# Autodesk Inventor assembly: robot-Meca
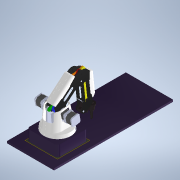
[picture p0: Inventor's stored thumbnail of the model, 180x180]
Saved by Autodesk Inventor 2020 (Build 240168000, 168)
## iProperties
Created: 2017-09
Part Number: robot-Meca
Document SubType Name: Assembly
Designer: bruno
Sending System: SolidWorks 2016
Last Author: Prof
Last Saved: 2018-10-31
Author: bruno
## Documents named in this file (11)
- C:\Users\bruno\Documents\1-Cours-2023-24\1SI\Robot-Dobot\Robot-meca\robot-Meca.iam
- C:\Users\bruno\Documents\1-Cours-2023-24\1SI\Robot-Dobot\Robot-meca\base^robot.iam
- C:\Users\bruno\Documents\1-Cours-2023-24\1SI\Robot-Dobot\Robot-meca\plateforme^robot.iam
- C:\Users\bruno\Documents\1-Cours-2023-24\1SI\Robot-Dobot\Robot-meca\bras inférieur^robot.iam
- C:\Users\bruno\Documents\1-Cours-2023-24\1SI\Robot-Dobot\Robot-meca\manivelle inférieure^robot.iam
- C:\Users\bruno\Documents\1-Cours-2023-24\1SI\Robot-Dobot\Robot-meca\biellette gauche^robot.iam
- C:\Users\bruno\Documents\1-Cours-2023-24\1SI\Robot-Dobot\Robot-meca\biellette droite^robot.iam
- C:\Users\bruno\Documents\1-Cours-2023-24\1SI\Robot-Dobot\Robot-meca\bras supérieur^robot.iam
- C:\Users\bruno\Documents\1-Cours-2023-24\1SI\Robot-Dobot\Robot-meca\basculeur^robot.iam
- C:\Users\bruno\Documents\1-Cours-2023-24\1SI\Robot-Dobot\Robot-meca\biellette avant^robot.iam
- C:\Users\bruno\Documents\1-Cours-2023-24\1SI\Robot-Dobot\Robot-meca\Stylo.iam
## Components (10 placed, 10 different names)
1. base:1 [sub-assembly] — Placage:4, Affleurement:1, Angle:1
2. plateforme:1 [sub-assembly] — Placage:3, Placage:4, Affleurement:1, Placage:5, Placage:6, Placage:7, Placage:8
3. bras inférieur:1 [sub-assembly] — Placage:7, Placage:8, Placage:9, Placage:10, Angle:1
4. manivelle inférieure:1 [sub-assembly] — Placage:1, Placage:2, Placage:3
5. biellette gauche:1 [sub-assembly] — Placage:5, Placage:6, Placage:11, Placage:16
6. biellette droite:1 [sub-assembly] — Placage:1, Placage:2, Placage:20, Placage:21
7. bras supérieur:1 [sub-assembly] — Placage:9, Placage:10, Placage:12, Placage:17, Placage:19, Placage:20, Placage:21
8. basculeur:1 [sub-assembly] — Placage:11, Placage:12, Placage:13, Placage:14, Placage:16
9. biellette avant:1 [sub-assembly] — Placage:13, Placage:14, Placage:18
10. Stylo:1 [sub-assembly] — Placage:17, Placage:18, Placage:19
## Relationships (22: Mate 20, Flush 1, Angle 1)
- Placage:1 [Mate]: manivelle inférieure:1 ↔ biellette droite:1
- Placage:2 [Mate]: manivelle inférieure:1 ↔ biellette droite:1
- Placage:3 [Mate]: plateforme:1 ↔ manivelle inférieure:1
- Placage:4 [Mate]: base:1 ↔ plateforme:1
- Affleurement:1 [Flush]: base:1 ↔ plateforme:1
- Placage:5 [Mate]: plateforme:1 ↔ biellette gauche:1
- Placage:6 [Mate]: plateforme:1 ↔ biellette gauche:1
- Placage:7 [Mate]: plateforme:1 ↔ bras inférieur:1
- Placage:8 [Mate]: plateforme:1 ↔ bras inférieur:1
- Placage:9 [Mate]: bras inférieur:1 ↔ bras supérieur:1
- Placage:10 [Mate]: bras inférieur:1 ↔ bras supérieur:1
- Placage:11 [Mate]: biellette gauche:1 ↔ basculeur:1
- Placage:12 [Mate]: bras supérieur:1 ↔ basculeur:1
- Placage:13 [Mate]: basculeur:1 ↔ biellette avant:1
- Placage:14 [Mate]: basculeur:1 ↔ biellette avant:1
- Placage:16 [Mate]: biellette gauche:1 ↔ basculeur:1
- Placage:17 [Mate]: bras supérieur:1 ↔ Stylo:1
- Placage:18 [Mate]: biellette avant:1 ↔ Stylo:1
- Placage:19 [Mate]: bras supérieur:1 ↔ Stylo:1
- Placage:20 [Mate]: biellette droite:1 ↔ bras supérieur:1
- Placage:21 [Mate]: biellette droite:1 ↔ bras supérieur:1
- Angle:1: base:1 ↔ bras inférieur:1
